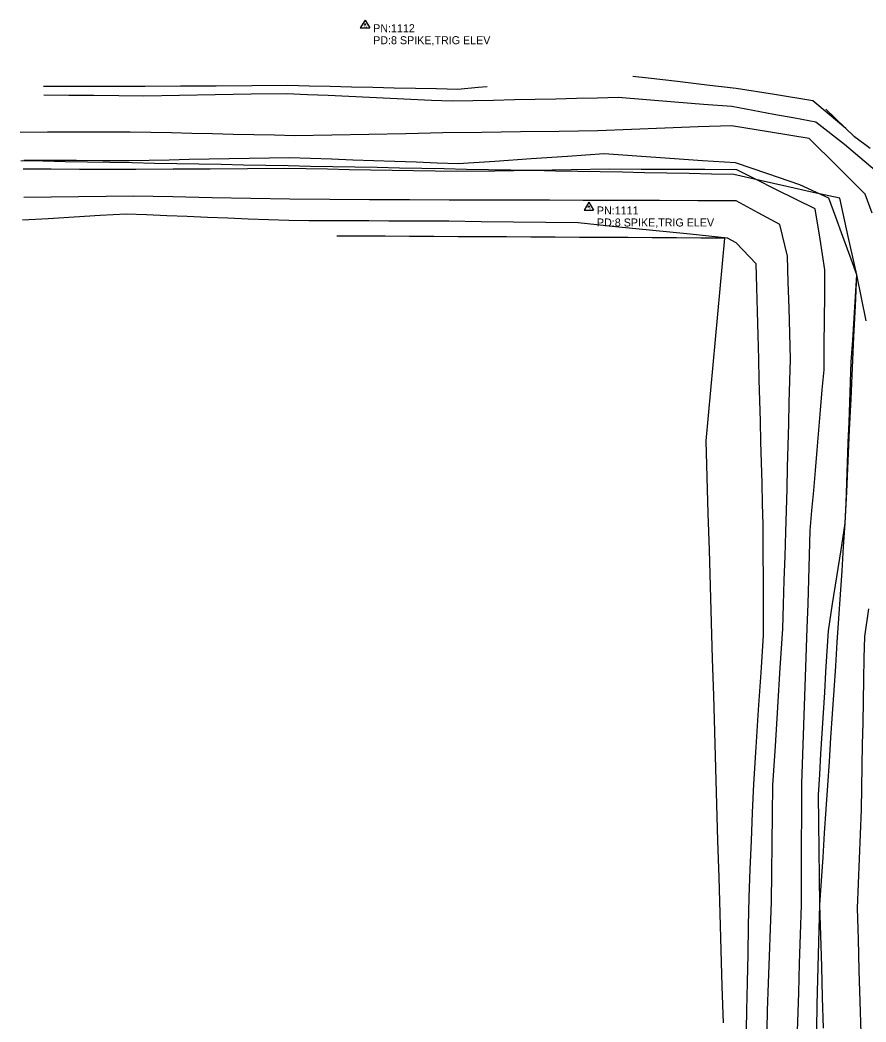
# Model space of a CAD drawing. Extents: x 1445297 to 1476720, y 2042269 to 2057889.
# Drawn here: x 1445451 to 1445979, y 2044127 to 2044753 of the extents above; entities that cross this region are included whole.
import ezdxf

# ---------------------------------------------------------------- set-up
doc = ezdxf.new("R2010")
doc.units = 0
for name, color, linetype in [('S_DITCHLINE', 7, 'Continuous'), ('S_LEVEE', 7, 'Continuous'), ('S_SECONDARY_CTL', 7, 'Continuous'), ('S_SECONDARY_CTL_ANNOT', 7, 'Continuous'), ('S_STREAM', 7, 'Continuous'), ('S_TREE', 7, 'Continuous')]:
    doc.layers.add(name, color=color, linetype=linetype)

msp = doc.modelspace()

# ---------------------------------------------------------------- linework, layer by layer
at = {"layer": 'S_DITCHLINE'}
for points in [[(1445984.59, 2044659.09), (1445975.02, 2044667.24), (1445965.45, 2044675.39), (1445947.53, 2044689.24), (1445934.42, 2044691.68), (1445921.31, 2044694.11), (1445908.2, 2044696.55), (1445895.09, 2044698.99), (1445877.35, 2044700.4), (1445859.6, 2044701.8), (1445841.86, 2044703.21), (1445824.12, 2044704.61), (1445811.16, 2044704.32), (1445798.2, 2044704.03), (1445785.24, 2044703.75), (1445772.28, 2044703.46), (1445759.32, 2044703.17), (1445746.36, 2044702.88), (1445733.41, 2044702.59), (1445720.45, 2044702.3), (1445707.55, 2044702.89), (1445694.65, 2044703.49), (1445681.75, 2044704.08), (1445668.86, 2044704.68), (1445655.96, 2044705.27), (1445643.06, 2044705.87), (1445630.17, 2044706.46), (1445617.27, 2044707.06), (1445594.9, 2044706.7), (1445572.53, 2044706.34), (1445550.16, 2044705.99), (1445527.79, 2044705.63), (1445512.2, 2044705.76), (1445496.61, 2044705.88), (1445481.02, 2044706.01), (1445465.43, 2044706.13)], [(1445982.9, 2044632.46), (1445978.35, 2044644.34), (1445960.94, 2044661.72), (1445943.53, 2044679.11), (1445919.23, 2044683.1), (1445894.92, 2044687.09), (1445874.08, 2044686.26), (1445853.24, 2044685.43), (1445832.39, 2044684.6), (1445811.55, 2044683.76), (1445787.33, 2044683.45), (1445763.11, 2044683.14), (1445738.9, 2044682.83), (1445714.68, 2044682.52), (1445691.58, 2044682.09), (1445668.49, 2044681.66), (1445645.4, 2044681.23), (1445622.3, 2044680.8), (1445609.43, 2044681.09), (1445596.56, 2044681.38), (1445583.69, 2044681.67), (1445570.81, 2044681.96), (1445557.94, 2044682.26), (1445545.07, 2044682.55), (1445532.2, 2044682.84), (1445519.32, 2044683.13), (1445502.14, 2044683.08), (1445484.95, 2044683.03), (1445467.76, 2044682.97), (1445450.57, 2044682.92)], [(1445978.98, 2044565.02), (1445976.11, 2044579.49), (1445973.25, 2044593.96), (1445968.87, 2044605.92), (1445964.5, 2044617.88), (1445960.13, 2044629.84), (1445955.75, 2044641.8), (1445937.69, 2044650.18), (1445917.58, 2044656.98), (1445897.46, 2044663.79), (1445876.93, 2044665.19), (1445856.4, 2044666.6), (1445835.86, 2044668.01), (1445815.33, 2044669.42), (1445792.58, 2044667.87), (1445769.82, 2044666.32), (1445747.07, 2044664.77), (1445724.31, 2044663.23), (1445711.12, 2044663.7), (1445697.93, 2044664.18), (1445684.74, 2044664.66), (1445671.55, 2044665.14), (1445658.36, 2044665.62), (1445645.17, 2044666.09), (1445631.98, 2044666.57), (1445618.79, 2044667.05), (1445606.28, 2044666.81), (1445593.77, 2044666.58), (1445581.27, 2044666.34), (1445568.76, 2044666.1), (1445556.25, 2044665.86), (1445543.75, 2044665.62), (1445531.24, 2044665.38), (1445518.73, 2044665.15), (1445502.3, 2044665.19), (1445485.86, 2044665.23), (1445469.43, 2044665.28), (1445453, 2044665.32)], [(1445952.45, 2044123.01), (1445951.88, 2044142.3), (1445951.3, 2044161.6), (1445950.73, 2044180.89), (1445950.16, 2044200.19), (1445949.94, 2044217.34), (1445949.73, 2044234.5), (1445949.51, 2044251.65), (1445949.29, 2044268.8), (1445950.06, 2044281.63), (1445950.83, 2044294.45), (1445951.6, 2044307.28), (1445952.37, 2044320.1), (1445953.14, 2044332.93), (1445953.9, 2044345.75), (1445954.67, 2044358.58), (1445955.44, 2044371.4), (1445958.08, 2044388.24), (1445960.71, 2044405.08), (1445963.35, 2044421.92), (1445965.99, 2044438.75), (1445966.46, 2044451.34), (1445966.94, 2044463.93), (1445967.41, 2044476.51), (1445967.88, 2044489.1), (1445968.36, 2044501.69), (1445968.83, 2044514.27), (1445969.31, 2044526.86), (1445969.78, 2044539.45), (1445970.65, 2044553.08), (1445971.51, 2044566.7), (1445972.38, 2044580.33), (1445973.25, 2044593.96)], [(1445975.96, 2044120.13), (1445975.37, 2044139.62), (1445974.77, 2044159.12), (1445974.18, 2044178.61), (1445973.58, 2044198.11), (1445974.2, 2044213.51), (1445974.81, 2044228.92), (1445975.43, 2044244.33), (1445976.04, 2044259.73), (1445976.3, 2044273.25), (1445976.57, 2044286.78), (1445976.83, 2044300.3), (1445977.1, 2044313.82), (1445977.36, 2044327.34), (1445977.62, 2044340.86), (1445977.89, 2044354.38), (1445978.15, 2044367.9), (1445980.65, 2044385.13)]]:
    msp.add_lwpolyline(points, dxfattribs=at)
at = {"layer": 'S_LEVEE'}
for points in [[(1445916.99, 2044110.19), (1445917.52, 2044134.16), (1445918.14, 2044151.12), (1445918.76, 2044168.09), (1445919.38, 2044185.05), (1445920, 2044202.01), (1445920.21, 2044220.22), (1445920.42, 2044238.42), (1445920.62, 2044256.63), (1445920.83, 2044274.83), (1445922.36, 2044299.29), (1445923.88, 2044323.75), (1445925.41, 2044348.21), (1445926.93, 2044372.67), (1445927.42, 2044387.78), (1445927.91, 2044402.88), (1445928.4, 2044417.99), (1445928.89, 2044433.1), (1445929.26, 2044446.61), (1445929.62, 2044460.12), (1445929.98, 2044473.63), (1445930.34, 2044487.14), (1445930.7, 2044500.65), (1445931.06, 2044514.16), (1445931.42, 2044527.66), (1445931.79, 2044541.17), (1445931.32, 2044557.24), (1445930.86, 2044573.3), (1445930.4, 2044589.37), (1445929.94, 2044605.43), (1445925.22, 2044625.24), (1445911.53, 2044632.69), (1445897.83, 2044640.14), (1445873.93, 2044640.21), (1445850.03, 2044640.28), (1445826.13, 2044640.35), (1445802.23, 2044640.41), (1445781.33, 2044640.44), (1445760.43, 2044640.47), (1445739.53, 2044640.5), (1445718.63, 2044640.53), (1445693.76, 2044640.67), (1445668.89, 2044640.82), (1445644.03, 2044640.96), (1445619.16, 2044641.11), (1445594.74, 2044641.58), (1445570.32, 2044642.05), (1445545.9, 2044642.52), (1445521.48, 2044642.99), (1445504.32, 2044642.82), (1445487.16, 2044642.65), (1445470, 2044642.48), (1445452.85, 2044642.3)], [(1445904.04, 2044110.36), (1445904.5, 2044134.03), (1445904.88, 2044151.68), (1445905.25, 2044169.33), (1445905.62, 2044186.98), (1445905.99, 2044204.63), (1445906.7, 2044222.35), (1445907.4, 2044240.07), (1445908.11, 2044257.78), (1445908.82, 2044275.5), (1445910.35, 2044298.76), (1445911.89, 2044322.01), (1445913.43, 2044345.27), (1445914.97, 2044368.53), (1445914.91, 2044385.87), (1445914.86, 2044403.21), (1445914.8, 2044420.55), (1445914.74, 2044437.89), (1445914.39, 2044450.81), (1445914.04, 2044463.73), (1445913.69, 2044476.64), (1445913.34, 2044489.56), (1445912.99, 2044502.48), (1445912.64, 2044515.39), (1445912.29, 2044528.31), (1445911.94, 2044541.23), (1445911.56, 2044556.13), (1445911.19, 2044571.03), (1445910.82, 2044585.94), (1445910.45, 2044600.84), (1445897.84, 2044613.83), (1445892.45, 2044616.81), (1445869.11, 2044619.18), (1445845.77, 2044621.55), (1445822.43, 2044623.91), (1445799.08, 2044626.28), (1445778.93, 2044626.54), (1445758.78, 2044626.81), (1445738.62, 2044627.08), (1445718.47, 2044627.34), (1445705.97, 2044627.39), (1445693.46, 2044627.44), (1445680.96, 2044627.48), (1445668.45, 2044627.53), (1445655.95, 2044627.58), (1445643.45, 2044627.63), (1445630.94, 2044627.67), (1445618.44, 2044627.72), (1445605.73, 2044628.23), (1445593.02, 2044628.75), (1445580.31, 2044629.26), (1445567.59, 2044629.77), (1445554.88, 2044630.28), (1445542.17, 2044630.8), (1445529.46, 2044631.31), (1445516.75, 2044631.82), (1445500.57, 2044630.86), (1445484.39, 2044629.91), (1445468.21, 2044628.95), (1445452.03, 2044627.99)]]:
    msp.add_lwpolyline(points, dxfattribs=at)
at = {"layer": 'S_SECONDARY_CTL'}
for p, q in [((1445666.12, 2044753.11), (1445663.11, 2044748.15)), ((1445666.12, 2044753.11), (1445669.07, 2044748.15)), ((1445663.11, 2044748.15), (1445669.07, 2044748.15)), ((1445805.89, 2044639.19), (1445802.88, 2044634.23)), ((1445802.88, 2044634.23), (1445808.84, 2044634.23)), ((1445805.89, 2044639.19), (1445808.84, 2044634.23))]:
    msp.add_line(p, q, dxfattribs=at)
for centre, radius in [((1445666.12, 2044750.5), 0.311), ((1445666.12, 2044750.5), 0.183), ((1445666.12, 2044750.5), 0.103), ((1445805.89, 2044636.58), 0.311), ((1445805.89, 2044636.58), 0.183), ((1445805.89, 2044636.58), 0.103)]:
    msp.add_circle(centre, radius, dxfattribs=at)
at = {"layer": 'S_STREAM'}
for points in [[(1445981.56, 2044672.84), (1445971.76, 2044680.13), (1445953.95, 2044697.37), (1445966.31, 2044685.24), (1445956.03, 2044693.97), (1445945.76, 2044702.69), (1445921.78, 2044706.52), (1445897.81, 2044710.36), (1445879.51, 2044712.49), (1445861.2, 2044714.62), (1445842.9, 2044716.74), (1445833.38, 2044717.85)], [(1445742.37, 2044711.39), (1445736.63, 2044710.87), (1445724.06, 2044709.72), (1445710.77, 2044710.03), (1445697.49, 2044710.33), (1445684.2, 2044710.63), (1445670.92, 2044710.94), (1445657.64, 2044711.24), (1445644.35, 2044711.55), (1445631.07, 2044711.85), (1445617.78, 2044712.16), (1445595.47, 2044712.01), (1445573.15, 2044711.86), (1445550.84, 2044711.72), (1445528.53, 2044711.57), (1445512.7, 2044711.59), (1445496.88, 2044711.61), (1445481.05, 2044711.63), (1445465.22, 2044711.64)], [(1445935.53, 2044104.1), (1445936.33, 2044127), (1445936.9, 2044145.22), (1445937.47, 2044163.45), (1445938.05, 2044181.67), (1445938.62, 2044199.89), (1445938.69, 2044218.9), (1445938.76, 2044237.91), (1445938.83, 2044256.91), (1445938.91, 2044275.92), (1445939.75, 2044300.19), (1445940.6, 2044324.46), (1445941.44, 2044348.73), (1445942.29, 2044373), (1445942.76, 2044388.26), (1445943.22, 2044403.51), (1445943.69, 2044418.76), (1445944.15, 2044434.02), (1445945.22, 2044446.57), (1445946.29, 2044459.12), (1445947.36, 2044471.68), (1445948.43, 2044484.23), (1445949.5, 2044496.79), (1445950.57, 2044509.34), (1445951.64, 2044521.89), (1445952.72, 2044534.45), (1445952.87, 2044550.11), (1445953.02, 2044565.77), (1445953.18, 2044581.43), (1445953.33, 2044597.09), (1445950.3, 2044616.06), (1445947.26, 2044635.04), (1445934.99, 2044641.16), (1445922.72, 2044647.29), (1445910.45, 2044653.41), (1445898.18, 2044659.54), (1445878.32, 2044659.62), (1445858.45, 2044659.69), (1445838.58, 2044659.77), (1445818.72, 2044659.85), (1445794.84, 2044659.48), (1445770.97, 2044659.1), (1445747.09, 2044658.73), (1445723.22, 2044658.35), (1445709.8, 2044658.59), (1445696.38, 2044658.84), (1445682.96, 2044659.08), (1445669.54, 2044659.32), (1445656.12, 2044659.56), (1445642.7, 2044659.8), (1445629.28, 2044660.04), (1445615.86, 2044660.28), (1445592.62, 2044660.12), (1445569.38, 2044659.97), (1445546.14, 2044659.81), (1445522.9, 2044659.66), (1445505.3, 2044659.72), (1445487.7, 2044659.79), (1445470.1, 2044659.85), (1445452.5, 2044659.92)]]:
    msp.add_lwpolyline(points, dxfattribs=at)
at = {"layer": 'S_TREE'}
for points in [[(1445948.15, 2044122.27), (1445948.55, 2044137.85), (1445948.95, 2044153.44), (1445949.35, 2044169.02), (1445949.76, 2044184.61), (1445950.16, 2044200.19), (1445951.15, 2044215.1), (1445952.14, 2044230.01), (1445953.13, 2044244.92), (1445954.12, 2044259.83), (1445955.1, 2044274.74), (1445956.09, 2044289.65), (1445957.08, 2044304.56), (1445958.07, 2044319.47), (1445959.06, 2044334.38), (1445960.05, 2044349.29), (1445961.04, 2044364.2), (1445962.03, 2044379.11), (1445963.02, 2044394.02), (1445964.01, 2044408.93), (1445965, 2044423.84), (1445965.99, 2044438.75), (1445966.9, 2044458.16), (1445967.8, 2044477.56), (1445968.71, 2044496.96), (1445969.62, 2044516.36), (1445970.52, 2044535.76), (1445971.43, 2044555.16), (1445972.34, 2044574.56), (1445973.25, 2044593.96), (1445967.89, 2044617.83), (1445962.54, 2044641.7), (1445945.99, 2044645.42), (1445929.45, 2044649.15), (1445912.91, 2044652.87), (1445896.36, 2044656.6), (1445882.44, 2044656.86), (1445868.53, 2044657.13), (1445854.61, 2044657.39), (1445840.69, 2044657.66), (1445826.77, 2044657.93), (1445812.85, 2044658.19), (1445798.94, 2044658.46), (1445785.02, 2044658.73), (1445771.1, 2044658.99), (1445757.18, 2044659.26), (1445743.26, 2044659.53), (1445729.35, 2044659.79), (1445715.43, 2044660.06), (1445701.51, 2044660.33), (1445687.59, 2044660.59), (1445673.67, 2044660.86), (1445659.76, 2044661.13), (1445645.84, 2044661.39), (1445631.92, 2044661.66), (1445618, 2044661.93), (1445604.08, 2044662.19), (1445590.17, 2044662.46), (1445576.25, 2044662.73), (1445562.33, 2044662.99), (1445548.41, 2044663.26), (1445534.49, 2044663.53), (1445520.58, 2044663.79), (1445506.66, 2044664.06), (1445492.74, 2044664.33), (1445478.82, 2044664.59), (1445464.9, 2044664.86), (1445450.99, 2044665.13)], [(1445889.86, 2044126.4), (1445889.19, 2044149.14), (1445888.51, 2044171.88), (1445887.84, 2044194.62), (1445887.17, 2044217.36), (1445886.5, 2044240.1), (1445885.82, 2044262.83), (1445885.15, 2044285.57), (1445884.48, 2044308.31), (1445883.81, 2044331.05), (1445883.14, 2044353.79), (1445882.46, 2044376.53), (1445881.79, 2044399.26), (1445881.12, 2044422), (1445880.45, 2044444.74), (1445879.78, 2044467.48), (1445879.1, 2044490.22), (1445880.57, 2044506.03), (1445882.04, 2044521.85), (1445883.5, 2044537.67), (1445884.97, 2044553.48), (1445886.44, 2044569.3), (1445887.9, 2044585.12), (1445889.37, 2044600.93), (1445890.84, 2044616.75), (1445875.69, 2044616.84), (1445860.53, 2044616.92), (1445845.38, 2044617.01), (1445830.23, 2044617.1), (1445815.08, 2044617.18), (1445799.93, 2044617.27), (1445784.77, 2044617.35), (1445769.62, 2044617.44), (1445754.47, 2044617.53), (1445739.32, 2044617.61), (1445724.16, 2044617.7), (1445709.01, 2044617.79), (1445693.86, 2044617.87), (1445678.71, 2044617.96), (1445663.56, 2044618.05), (1445648.4, 2044618.13)]]:
    msp.add_lwpolyline(points, dxfattribs=at)

# ---------------------------------------------------------------- texts
at = {"layer": 'S_SECONDARY_CTL'}
for p in [(1445664.92, 2044748.48), (1445804.68, 2044634.57)]:
    msp.add_text('TV', height=1.5, dxfattribs=at).set_placement(p)
at = {"layer": 'S_SECONDARY_CTL_ANNOT'}
for s, p in [('PN:1112', (1445671.12, 2044745.5)), ('PD:8 SPIKE,TRIG ELEV', (1445671.12, 2044738)), ('PN:1111', (1445810.89, 2044631.58)), ('PD:8 SPIKE,TRIG ELEV', (1445810.89, 2044624.08))]:
    msp.add_text(s, height=5, dxfattribs=at).set_placement(p)

doc.saveas('drawing.dxf')
